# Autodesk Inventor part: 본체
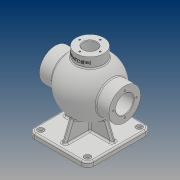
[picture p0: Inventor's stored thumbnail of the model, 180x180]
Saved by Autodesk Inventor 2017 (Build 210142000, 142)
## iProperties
Part Number: 본체
Material: 일반
Document SubType Name: Modeling
Designer: 13
Density: 1 g/cm^3
Appearance: 기본값
Author: 13
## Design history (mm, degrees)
revolve "회전1" stored, may be unused: angle "d13" = 90 deg
node "작업 평면1"
sketch "스케치3"
  geometry: L1 (-57.5, 62.5)-(57.5, 62.5); L2 (57.5, 62.5)-(57.5, -62.5); L3 (57.5, -62.5)-(-57.5, -62.5); L4 (-57.5, -62.5)-(-57.5, 62.5); L5 (-57.5, 62.5)-(57.5, -62.5); L6 (57.5, 62.5)-(-57.5, -62.5); 1 further point
  constraints: 12 end point, 2 midpoint, 2 parallel, 1 horizontal, 1 perpendicular
  dimensions: "d20" = 115 distance of L2.end L3.end; "d21" = 125 distance of L1.end L2.end
extrude "돌출1" join sketch "스케치3" distance "d22" = 10; taper "d23" = 0 deg
sketch "스케치4"
  geometry: L1 (-47.5, 4)-(47.5, 4); L2 (47.5, 4)-(47.5, -4); L3 (47.5, -4)-(-47.5, -4); L4 (-47.5, -4)-(-47.5, 4); L5 (-47.5, 4)-(47.5, -4); L6 (47.5, 4)-(-47.5, -4); L7 (-4, 52.5)-(4, 52.5); L8 (4, 52.5)-(4, -52.5); L9 (4, -52.5)-(-4, -52.5); L10 (-4, -52.5)-(-4, 52.5); L11 (-4, 52.5)-(4, -52.5); L12 (4, 52.5)-(-4, -52.5); L13 (57.5, 62.5)-(57.5, -62.5) reference; L14 (-57.5, 62.5)-(57.5, 62.5) reference; 1 further point
  constraints: 24 end point, 4 midpoint, 4 parallel, 2 horizontal, 2 perpendicular
  dimensions: "d24" = 8 distance of L1.end L2.end; "d25" = 8 distance of L7.start L7.end; "d26" = 10 distance between parallel lines of L2 L13; "d27" = 10 distance between parallel lines of L14 L7
extrude "돌출2" join sketch "스케치4" stored distance "d28" = 10; taper "d29" = 0 deg
feature "면 기울기1" dims angle "d30" = 22 deg
fillet "모깎기1" dims "d31" = 3
fillet "모깎기2" dims "d32" = 3
fillet "모깎기3" dims "d33" = 3
fillet "모깎기4" dims "d34" = 3
node "작업 평면2"
sketch "스케치5"
  geometry: C1 r 27 at (0, 0); 1 further point
  constraints: 1 centre point, 1 coincident
  dimensions: "d36" = 54 diameter of C1
extrude "돌출3" join sketch "스케치5" stored distance "d37" = 10; taper "d38" = 0 deg
sketch "스케치6"
  geometry: C1 r 13 at (0, 0); 1 further point
  constraints: 1 centre point, 1 coincident
  dimensions: "d39" = 26 diameter of C1
extrude "돌출4" cut sketch "스케치6" distance "d40" = 30; taper "d41" = 0 deg
fillet "모깎기5" dims "d42" = 12
fillet "모깎기6" dims "d43" = 3
chamfer "모따기1" distance "d44" = 1; stored, may be unused: second distance "d45" = 2, angle "d46" = 45 deg
fillet "모깎기7" dims "d47" = 3
sketch "스케치8"
  geometry: L1 (-45.5, -62.5)-(45.5, -62.5) reference; L2 (57.5, -50.5)-(57.5, 50.5) reference; C1 r 6 at (45.5, -50.5); 1 further point
  constraints: 1 centre point
  dimensions: "d48" = 12 diameter of C1; "d50" = 12 distance from line of L2 C1.centre; "d51" = 12 distance from line of L1 C1.centre
extrude "돌출5" cut sketch "스케치8" distance "d52" = 3; taper "d53" = 0 deg
sketch "스케치9"
  geometry: L1 (12, 101)-(12, 0) reference; L2 (0, -12)-(-91, -12) reference; C1 r 4 at (0, 0); 1 further point
  constraints: 1 centre point
  dimensions: "d54" = 8 diameter of C1; "d55" = 12 distance from line of L1 C1.centre; "d56" = 12 distance from line of L2 C1.centre
extrude "돌출6" cut sketch "스케치9" stored distance "d57" = 3; taper "d58" = 0 deg
sketch "스케치11"
  geometry: 2 further points
  constraints: 1 horizontal alignment
  dimensions: "d65" = 22.5 distance of point (0, 0) point (-22.5, 0)
hole "구멍1" sketch "스케치11" at (-22.5, 0) diameter "d66" = 3.242; stored, may be unused: countersink angle "d70" = 90 deg, drill point angle "d72" = 118 deg; dims "d67" = 12, "d68" = 4, "d69" = 2, "d71" = 15
sketch "스케치12"
  geometry: 2 further points
  constraints: 1 horizontal alignment
  dimensions: "d76" = 24 distance of point (0, 0) point (24, 0)
hole "구멍2" sketch "스케치12" at (24, 0) diameter "d77" = 3.242; stored, may be unused: countersink angle "d81" = 90 deg, drill point angle "d83" = 118 deg; dims "d78" = 16, "d79" = 4, "d80" = 2, "d82" = 19
sketch "스케치13"
  geometry: 2 further points
  constraints: 1 vertical alignment
  dimensions: "d87" = 20 distance of point (0, 0) point (0, 20)
hole "구멍3" sketch "스케치13" at (0, 20) diameter "d88" = 3.242; stored, may be unused: countersink angle "d92" = 90 deg, drill point angle "d94" = 118 deg; dims "d89" = 9, "d90" = 4, "d91" = 2, "d93" = 11
node "작업 평면3"
sketch "스케치14"
  geometry: L1 (-27, 65)-(27, 65) reference; L2 (-27, 65)-(-27, 50.285); L3 (-27, 65)-(-27, 47.286) reference; 2 further points
  constraints: 2 end point, 1 point on line, 1 other
  dimensions: "d103" = 10 distance from line of point (0, 55) L1; "d104" = 27 distance from line of L2 point (0, 55)
feature "엠보싱2" sketch "스케치14" dims "d1" = 136, "d8" = 106, "d9" = 86, "d11" = 62, "d17" = 35, "d101" = 0.5, "d102" = 0, "d105" = 16, "d106" = 1.75, "d107" = 37, "d108" = 35
node "솔리드1"
pattern_linear "직사각형 패턴1" dims "d61" = 101, "d64" = 91
pattern_circular "원형 패턴3" dims angle "d96" = 360 deg
pattern_circular "원형 패턴4" dims angle "d110" = 360 deg
pattern_circular "원형 패턴5" dims angle "d113" = 360 deg
sketch "스케치2"
  geometry: L1 (68, 0)-(-68, 0); L2 (68, 31)-(42.988, 31); L3 (-42.988, 31)-(-68, 31); L4 (-68, 31)-(-68, 17.5); L5 (68, 31)-(68, 17.5); L6 (-68, 17.5)-(-52, 17.5); L7 (-52, 17.5)-(-39.278, 17.5); L8 (68, 17.5)-(52, 17.5); L9 (52, 17.5)-(52, 18.5); L10 (52, 18.5)-(50.25, 18.5); L11 (50.25, 18.5)-(50.25, 17.5); L12 (50.25, 17.5)-(39.278, 17.5); A1 r 53 centre (0, 0) between (42.988, 31) and (-42.988, 31); A2 r 43 centre (0, 0) between (39.278, 17.5) and (-39.278, 17.5); 6 further points
  constraints: 25 end point, 7 horizontal, 5 midpoint, 4 point on circle, 4 vertical, 3 coincident, 3 point on line, 2 centre point, 2 vertical alignment, 1 horizontal alignment
  dimensions: "d1" = 136 distance of L1.start L1.end; "d8" = 106 diameter of A1; "d9" = 86 diameter of A2; "d11" = 62 diameter of L3 L1; "d17" = 35 diameter of L6 L1; "d105" = 16 distance of L5.end L8.end; "d106" = 1.75 distance of L9.end L10.end; "d107" = 37 diameter of L10 L1; "d108" = 35 diameter of L8 L1
other parameters: "d2" = 106, "d19" = -85, "d35" = 65
